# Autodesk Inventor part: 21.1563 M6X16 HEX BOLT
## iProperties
Created: 2012-03
Part Number: 21.1563 M6X16 HEX BOLT
Document SubType Name: Modeling
Designer: Administrator
Density: 7.85 g/cm^3
Material: Steel
Mass: 6.23611 g
Surface Area: 6.02039 cm^2
Volume: 0.794409 cm^3
Author: Administrator
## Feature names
1. Base1
